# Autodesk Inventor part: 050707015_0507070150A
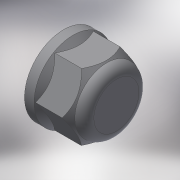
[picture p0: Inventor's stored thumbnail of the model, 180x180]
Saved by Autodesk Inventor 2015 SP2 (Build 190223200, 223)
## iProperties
Created: 2017-05
Part Number: 050707015_0507070150A
Material: Generic
Description: PLASSON CAP 1.1/2"
Document SubType Name: Modeling
Designer: KIM
Density: 1 g/cm^3
Appearance: Default
Author: KIM
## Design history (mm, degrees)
derived "050707.ipt"
feature "Solid1::050707.ipt"
tag "TaggingFeature1"
body "Solid1"
other parameters: "d0" = 34, "d1" = 2.1, "d2" = 44.845, "d3" = 21, "d4" = 2.1, "d5" = 135 deg, "d6" = 49.3295, "d7" = 65, "d8" = 55.25, "d9" = 53.3, "d10" = 135 deg, "d11" = 6.3, "d13" = 6.3, "d16" = 0, "Rp_" = 44.845, "E_" = 65, "H_" = 34, "l_2" = 21
